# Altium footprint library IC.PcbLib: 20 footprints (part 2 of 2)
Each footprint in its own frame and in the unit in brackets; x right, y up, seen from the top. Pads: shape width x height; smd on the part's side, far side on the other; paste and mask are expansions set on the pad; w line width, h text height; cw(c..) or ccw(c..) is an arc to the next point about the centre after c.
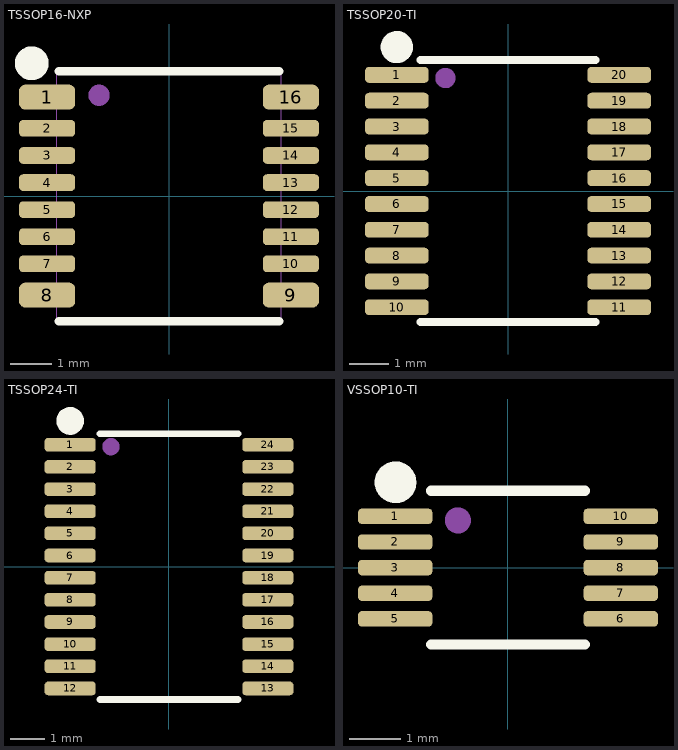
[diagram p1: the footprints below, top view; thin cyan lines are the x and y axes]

## TSSOP16-NXP [mm]
height 1.1
pads (16):
  rrect50% 1.35x0.6 smd paste+0 mask+0.05: 1(-2.925,2.375) 8(-2.925,-2.375) 9(2.925,-2.375) 16(2.925,2.375)
  rrect50% 1.35x0.4 smd paste+0 mask+0.05: 2(-2.925,1.625) 3(-2.925,0.975) 4(-2.925,0.325) 5(-2.925,-0.325) 6(-2.925,-0.975) 7(-2.925,-1.625) 10(2.925,-1.625) 11(2.925,-0.975) 12(2.925,-0.325) 13(2.925,0.325) 14(2.925,0.975) 15(2.925,1.625)
Top Overlay:
  circle w0.406: c-3.293,3.188 r0.203
  lines w0.203: -2.65,-3 2.65,-3 ; -2.65,3 2.65,3
Mechanical 13:
  circle w0.254: c-1.676,2.421 r0.127
  lines w0.025: -2.7,-3 2.7,-3 2.7,3 -2.7,3 -2.7,-3
  text ".Designator" at 0,2.7 h1.02

## TSSOP20-TI [mm]
height 1.2
pads (20):
  rrect50% 1.6x0.4 smd mask+0.05: 1(-2.8,2.925) 2(-2.8,2.275) 3(-2.8,1.625) 4(-2.8,0.975) 5(-2.8,0.325) 6(-2.8,-0.325) 7(-2.8,-0.975) 8(-2.8,-1.625) 9(-2.8,-2.275) 10(-2.8,-2.925) 11(2.8,-2.925) 12(2.8,-2.275) 13(2.8,-1.625) 14(2.8,-0.975) 15(2.8,-0.325) 16(2.8,0.325) 17(2.8,0.975) 18(2.8,1.625) 19(2.8,2.275) 20(2.8,2.925)
Top Overlay:
  circle w0.406: c-2.8,3.625 r0.203
  lines w0.2: -2.2,-3.3 2.2,-3.3 ; -2.2,3.3 2.2,3.3
Mechanical 13:
  circle w0.254: c-1.576,2.846 r0.127
  text ".Designator" at -0.4,3.225 h1.02

## TSSOP24-TI [mm]
height 1.2
pads (24):
  rrect50% 1.5x0.4 smd mask+0.05: 1(-2.9,3.575) 2(-2.9,2.925) 3(-2.9,2.275) 4(-2.9,1.625) 5(-2.9,0.975) 6(-2.9,0.325) 7(-2.9,-0.325) 8(-2.9,-0.975) 9(-2.9,-1.625) 10(-2.9,-2.275) 11(-2.9,-2.925) 12(-2.9,-3.575) 13(2.9,-3.575) 14(2.9,-2.925) 15(2.9,-2.275) 16(2.9,-1.625) 17(2.9,-0.975) 18(2.9,-0.325) 19(2.9,0.325) 20(2.9,0.975) 21(2.9,1.625) 22(2.9,2.275) 23(2.9,2.925) 24(2.9,3.575)
Top Overlay:
  circle w0.406: c-2.9,4.275 r0.203
  lines w0.2: -2.025,-3.9 2.025,-3.9 ; -2.025,3.9 2.025,3.9
Mechanical 13:
  circle w0.254: c-1.701,3.521 r0.127
  text ".Designator" at -0.425,3.7 h1.02

## VSSOP10-TI [mm]
pads (10):
  rrect50% 1.45x0.3 smd mask+0.051: 1(-2.2,1) 2(-2.2,0.5) 3(-2.2,0) 4(-2.2,-0.5) 5(-2.2,-1) 6(2.2,-1) 7(2.2,-0.5) 8(2.2,0) 9(2.2,0.5) 10(2.2,1)
Top Overlay:
  circle w0.406: c-2.193,1.663 r0.203
  lines w0.2: -1.5,-1.5 1.5,-1.5 ; -1.5,1.5 1.5,1.5
Mechanical 13:
  circle w0.254: c-0.976,0.921 r0.127
  text ".Designator" at -0.2,1.3 h1.02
